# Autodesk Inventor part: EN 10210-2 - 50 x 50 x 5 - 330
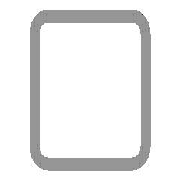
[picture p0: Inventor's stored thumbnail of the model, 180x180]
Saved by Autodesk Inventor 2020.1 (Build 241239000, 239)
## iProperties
Created: 2019-01
Part Number: EN 10210-2 - 50 x 50 x 5 - 330
Material: Stahl, weich
Description: Rohrleitung
Document SubType Name: Modeling
Standard: DIN
Designer: lutzd
Standard Revision: 2006-07
Standards Organization: DIN
Language: de-DE
Size Designation: 50 x 50 x 5
Categories: <MemberInstance><Categories><Category DisplayName="Profile" InternalName="089c4875-fa83-4c05-b084-43b9cc11f5ed" Mnemonic="GRDR"><CategoryParameter DisplayName="
Stock Number: 50 x 50 x 5
Mass: 2226.55 g
Surface Area: 1128.25 cm^2
Volume: 283.636 cm^3
Density: 7.85 g/cm^3
Appearance: Halbpoliert
_CCFamilyMember: 16
_CCFamilyDisplayName: DIN EN 10210-2 (USAS B17.1 quadratisch) - Rohrleitung — In Klammern angegebene Größen wurden aufgehoben
_FrameMemberDoc: Frame Member File
_Version: 15.0.0
_GetPNFromCC: 1
IsCustomPart: 1
G_L: 330,000 mm
G_W: 50,000 mm
G_H: 50,000 mm
DocNumber: ADSK-014174
Folder: .
Dimensions: 50x50x330 mm
Mass: 2,227 kg
Title: Profil-Bauteil
Author: lutzd
Revision Number: -
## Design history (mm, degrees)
node "Startebene"
node "Endebene"
sketch "Skizze"
  geometry: L1 (-25, -17.5)-(-25, 17.5); L2 (-17.5, 25)-(17.5, 25); L3 (25, 17.5)-(25, -17.5); L4 (17.5, -25)-(-17.5, -25); L5 (-15, 20)-(15, 20); L6 (20, 15)-(20, -15); L7 (15, -20)-(-15, -20); L8 (-20, -15)-(-20, 15); L9 (0, 37.175)-(0, -37.175) reference; L10 (-37.175, 0)-(37.175, 0) reference; A1 r 7.5 centre (-17.5, -17.5) between (-25, -17.5) and (-17.5, -25); A2 r 7.5 centre (-17.5, 17.5) between (-17.5, 25) and (-25, 17.5); A3 r 7.5 centre (17.5, 17.5) between (25, 17.5) and (17.5, 25); A4 r 7.5 centre (17.5, -17.5) between (17.5, -25) and (25, -17.5); A5 r 5 centre (-15, -15) between (-20, -15) and (-15, -20); A6 r 5 centre (-15, 15) between (-15, 20) and (-20, 15); A7 r 5 centre (15, 15) between (20, 15) and (15, 20); A8 r 5 centre (15, -15) between (15, -20) and (20, -15)
  constraints: 16 end point, 16 point on circle, 16 tangent, 8 centre point, 6 equal radius, 4 parallel, 2 perpendicular, 2 other
  dimensions: "d7" = 7.5 radius of A1 (= G_IR); "d10" = 50 distance between parallel lines of L2 L4 (= G_H); "d11" = 50 distance between parallel lines of L1 L3 (= G_W); "d12" = 5 distance between parallel lines of L3 L6 (= G_T); "d15" = 25 distance between parallel lines of L2 L10 (= 0.5 x d10); "d16" = 25 distance between parallel lines of L9 L3 (= 0.5 x d11); "d19" = 5 radius of A5 (= G_T); "d20" = 5 distance between parallel lines of L4 L7 (= G_T)
extrude "Körper" new body sketch "Skizze" stored distance "d3" = 330 (= G_L); taper "d4" = 0 deg
node "Driven Length"
  sketch "Sketch3"
    geometry: L1 (0, 0)-(10, 0) reference
    constraints: 2 end point, 1 horizontal
  workplane "Work Plane3"
  sketch "Sketch4"
    geometry: L1 (-2, 25)-(12, 25) reference; L2 (-2, 355)-(12, 355) reference
    dimensions: "d18" = 330 distance between parallel lines of L1 L2 (derived)
workplane "Arbeitsebene4"
feature "Trennen1"
sketch "Skizze5"
  geometry: L1 (0, 35)-(0, 0) reference; L2 (18.5, 34)-(51.5, 34); L3 (51.5, 34)-(51.5, 1); L4 (51.5, 1)-(18.5, 1); L5 (18.5, 1)-(18.5, 34); 8 further points
  constraints: 8 end point, 4 midpoint, 2 coincident, 2 horizontal alignment, 2 parallel, 1 horizontal, 1 perpendicular, 1 vertical alignment
  dimensions: "d21" = 33 distance of L2.start L2.end; "d22" = 33 distance of L2.end L3.end; "d37" = 35 distance from line of L1 point (35, 17.5)
hole "Bohrung1" sketch "Skizze5" diameter "d23" = 22; stored, may be unused: countersink angle "d27" = 90 deg, drill point angle "d29" = 118 deg; dims "d24" = 6, "d25" = 4, "d26" = 2, "d28" = 8
hole "Bohrung2" sketch "Skizze5" diameter "d30" = 6.4; stored, may be unused: countersink angle "d34" = 90 deg, drill point angle "d36" = 118 deg; dims "d31" = 6, "d32" = 4, "d33" = 2, "d35" = 8
body "Solid1"
other parameters: "G_W" = 50 [user parameter; used in 1 equation term], "G_H" = 50 [user parameter; used in 1 equation term], "G_T" = 5 [user parameter; used in 3 equation terms], "G_IR" = 7.5 [user parameter; used in 1 equation term], "G_L" = 330 (= d18) [user parameter; used in 1 equation term], "G_OFFSET_START" = -25 [user parameter; used in 1 equation term], "G_OFFSET_END" = 0 [user parameter; used in 1 equation term], "d13" = 25 (= -G_OFFSET_START), "d14" = 355 (= G_OFFSET_END + B_L), "B_L" = 355 [user parameter; used in 1 equation term], "d17" = 90 deg
